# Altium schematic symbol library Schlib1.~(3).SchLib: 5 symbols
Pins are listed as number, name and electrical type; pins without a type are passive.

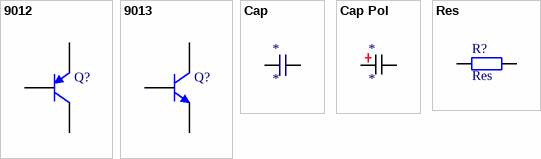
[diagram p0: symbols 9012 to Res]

## 9012
designator Q?  (value not drawn)
PNP General Purpose Amplifier
pins: 1 E, 2 B, 3 C

## 9013
designator Q?  (value not drawn)
NPN General Purpose Amplifier
pins: 1 E, 2 B, 3 C

## Cap
designator *
pins: 1, 2

## Cap Pol
designator *
pins: 1, 2

## Res
designator R?
Resistor; Value: 1K
pins: 1, 2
